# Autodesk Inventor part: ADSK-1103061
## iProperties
Shininess: 50.0
Length Units: 11272
Angle Units: 11279
Time Units: 11290
Mass Units: 11286
Length Display Precision: 4
Angle Display Precision: 2
Compacted: True
Created: 2000-08
Part Number: ADSK-1103061
Document SubType Name: Modeling
Description: EXHAUST PIPE - SIDE
Mass: 7.73957 g
Surface Area: 233.725 cm^2
Volume: 7.73957 cm^3
Density: 1 g/cm^3
Density: 0.0
Volumn: 0.0
Area: 0.0
PropertySet Name: Model Information
Control State: 0
Master: False
Checked Out: False
